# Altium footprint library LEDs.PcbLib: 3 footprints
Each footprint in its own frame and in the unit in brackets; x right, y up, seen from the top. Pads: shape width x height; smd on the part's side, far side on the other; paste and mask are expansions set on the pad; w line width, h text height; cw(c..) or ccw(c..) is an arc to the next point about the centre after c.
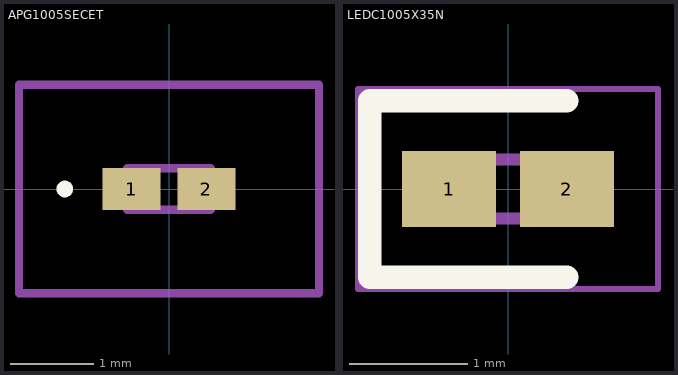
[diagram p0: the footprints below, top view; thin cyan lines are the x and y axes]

## APG1005SECET [mm]
pads (2):
  rect 0.7x0.5 smd: 1(-0.45,0) 2(0.45,0)
Top Overlay:
  lines w0.1: -1.3,0 ccw(c-1.25,0) -1.2,0 ccw(c-1.25,0) -1.3,0
Mechanical 13:
  lines w0.1: -0.5,-0.25 -0.5,0.25 0.5,0.25 0.5,-0.25 -0.5,-0.25
Mechanical 15:
  lines w0.1: -1.8,-1.25 -1.8,1.25 1.8,1.25 1.8,-1.25 -1.8,-1.25
3D body "APG1005SEC_E-T.stp": height 0.35, standoff 0, extent -0.5,-0.25 0.5,0.25

## LEDC1005X35N [mm]
pads (2):
  rect 0.8x0.65 smd: 1(-0.5,0) 2(0.5,0)
Top Overlay:
  lines w0.2: 0.5,-0.75 -1.175,-0.75 -1.175,0.75 0.5,0.75
Mechanical 13:
  lines w0.1: -0.5,0.083 -0.333,0.25 ; -0.5,-0.25 -0.5,0.25 0.5,0.25 0.5,-0.25 -0.5,-0.25
Mechanical 15:
  lines w0.05: -1.275,-0.85 -1.275,0.85 1.275,0.85 1.275,-0.85 -1.275,-0.85
3D body "VLMG1500-GS08.stp": height 0.5, standoff 0, extent -0.53,-0.17 0.47,0.18

## PCBComponent_1 [mm]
